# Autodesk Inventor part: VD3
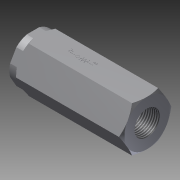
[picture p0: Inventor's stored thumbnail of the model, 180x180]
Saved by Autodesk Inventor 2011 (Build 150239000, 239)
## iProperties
Created: 2012-01
Part Number: VD3
Document SubType Name: Modeling
Designer: khramov
Density: 1 g/cm^3
Author: khramov
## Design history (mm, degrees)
derived "VD3_W1_30.ipt"
feature "Твердое тело1::VD3_W1_30.ipt" dims "d0" = 10
tag "Элемент создания маркировки1"
node "Твердое тело1"
